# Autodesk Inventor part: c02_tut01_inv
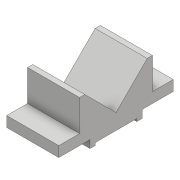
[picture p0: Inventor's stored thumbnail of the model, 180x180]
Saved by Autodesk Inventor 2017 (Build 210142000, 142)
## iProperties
Created: 2016-07
Part Number: c02_tut01_inv
Material: Generic
Document SubType Name: Modeling
Designer: Sandeep
Density: 1 g/cm^3
Appearance: Default
Author: Sandeep
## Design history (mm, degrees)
sketch "Sketch1"
  geometry: L1 (-2.5, 0)-(-5.5, 0); L2 (-5.5, 0)-(-5.5, 1); L3 (-5.5, 1)-(-3.5, 1); L4 (-3.5, 1)-(-3.5, 4); L5 (-3.5, 4)-(-3, 4); L6 (-3, 4)-(0, 1); L7 (0, 1)-(3, 4); L8 (3, 4)-(3.5, 4); L9 (3.5, 4)-(3.5, 1); L10 (3.5, 1)-(5.5, 1); L11 (5.5, 1)-(5.5, 0); L12 (5.5, 0)-(2.5, 0); L13 (2.5, 0)-(2.5, -0.75); L14 (2.5, -0.75)-(2, -0.75); L15 (2, -0.75)-(2, -0.5); L16 (2, -0.5)-(-2, -0.5); L17 (-2, -0.5)-(-2, -0.75); L18 (-2, -0.75)-(-2.5, -0.75); L19 (-2.5, -0.75)-(-2.5, 0); L20 (0, 0)-(0, 5.537); L21 (0, 0)-(-5.88, 0)
  constraints: 42 end point, 13 perpendicular, 10 point on line, 2 horizontal, 1 vertical, 8 other
  dimensions: "d0" = 4 distance of L15.end L16.end; "d1" = 0.5 distance of L13.end L14.end; "d2" = 3 distance of L1.start L1.end; "d3" = 1 distance from line of L1.end L3; "d4" = 3 distance between parallel lines of L5 L3; "d5" = 0.5 distance of L4.end L5.end; "d6" = 2 distance from line of L9 L10.end; "d7" = 0.25 distance between parallel lines of L14 L16; "d8" = 0.75 distance between parallel lines of L12 L14
extrude "Extrusion1" new body sketch "Sketch1" distance "d9" = 5; taper "d10" = 0 deg
body "Solid1"
